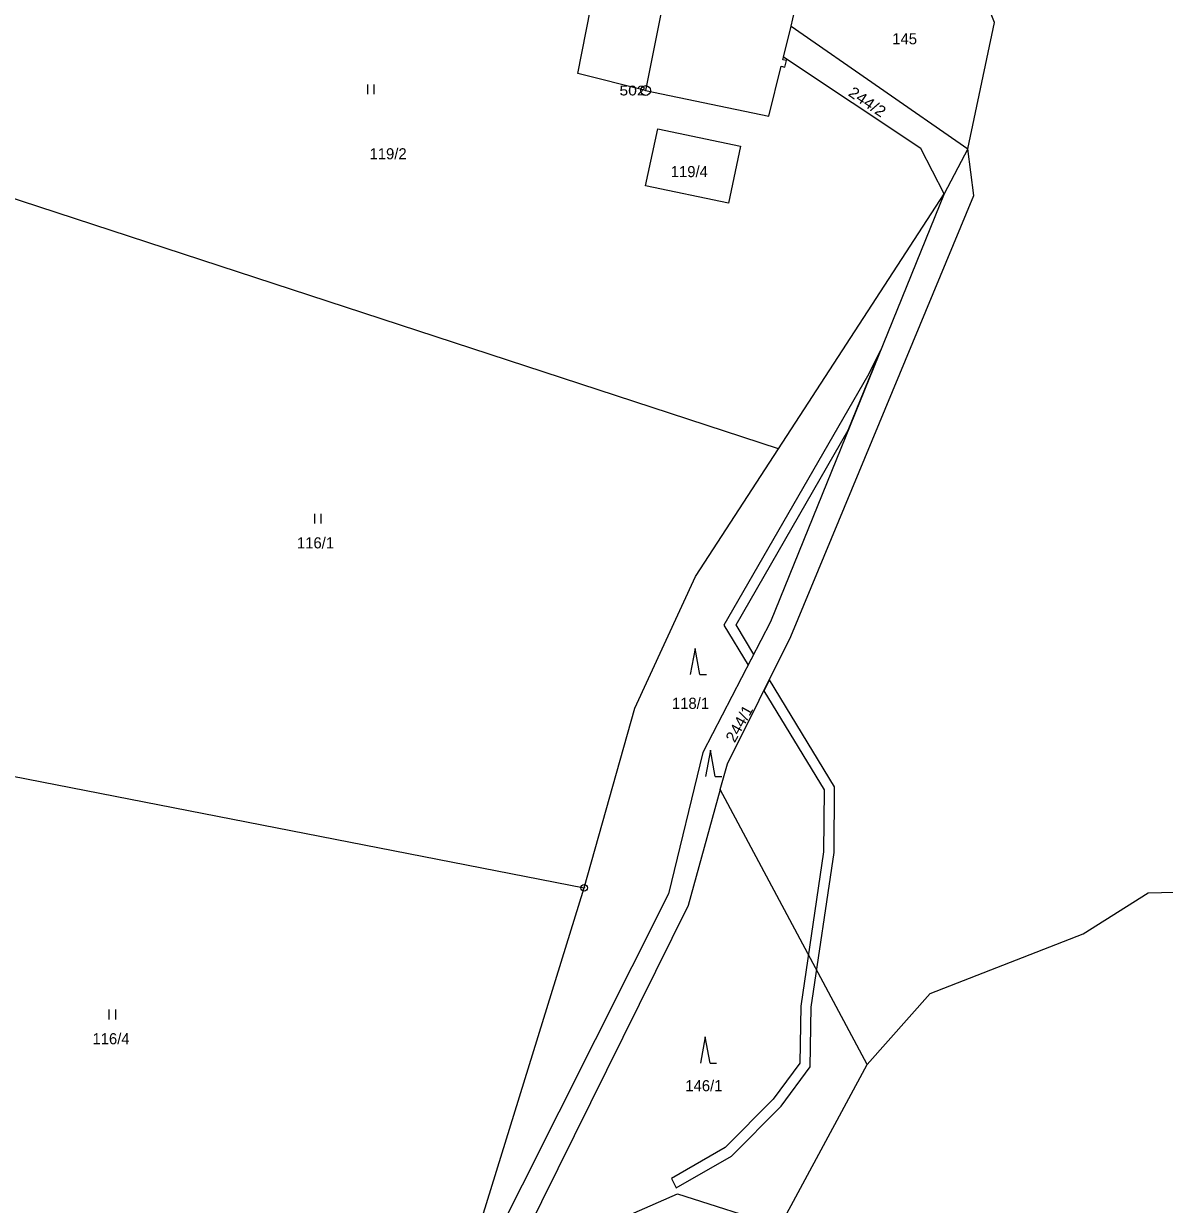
# Model space of a CAD drawing. Extents: x -632162 to -629607, y -1101195 to -1098670.
# Drawn here: x -631847.3 to -631672.5, y -1099345.9 to -1099165 of the extents above; entities that cross this region are included whole.
import ezdxf
from ezdxf.enums import TextEntityAlignment as Align

# ---------------------------------------------------------------- set-up
doc = ezdxf.new("R2010")
doc.units = 0
doc.header["$LTSCALE"] = 0.68
for name, color, linetype, lineweight in [('1', 7, 'Continuous', 25), ('13', 7, 'Continuous', 13), ('3', 7, 'Continuous', 25), ('8', 7, 'Continuous', 25)]:
    doc.layers.add(name, color=color, linetype=linetype, lineweight=lineweight)
doc.layers.add('2', color=7, linetype='Continuous')

msp = doc.modelspace()

# ---------------------------------------------------------------- linework, layer by layer
at = {"layer": '1'}
for p, q in [((-631729.7, -1099165.43), (-631702.64, -1099184.24)), ((-631731.64, -1099230.17), (-631706.26, -1099191.13)), ((-631862.77, -1099277.6), (-631761.39, -1099297.42))]:
    msp.add_line(p, q, dxfattribs=at)
for points in [[(-631751.98, -1099175.29), (-631762.35, -1099172.67), (-631759.79, -1099159.42), (-631759.55, -1099153.52), (-631762.37, -1099148.37), (-631767.41, -1099145.48), (-631784.49, -1099142.91), (-631791.78, -1099142.74), (-631798.56, -1099143.3)], [(-631729.42, -1099164.29), (-631726.24, -1099151.44), (-631745.62, -1099145.76), (-631748.79, -1099157.18), (-631748.51, -1099157.88), (-631751.98, -1099175.29)], [(-631702.64, -1099184.24), (-631698.52, -1099164.87), (-631700.96, -1099158.83)], [(-631730.88, -1099170.16), (-631729.7, -1099165.43), (-631729.42, -1099164.29)], [(-631751.98, -1099175.29), (-631733.12, -1099179.2), (-631731.22, -1099171.55), (-631730.66, -1099171.69), (-631730.39, -1099170.71), (-631730.98, -1099170.57), (-631730.88, -1099170.16)], [(-631706.26, -1099191.13), (-631709.81, -1099184.15), (-631730.88, -1099170.16)], [(-631740.55, -1099282.38), (-631739.45, -1099278.42), (-631729.73, -1099258.93), (-631701.72, -1099191.37), (-631702.64, -1099184.24), (-631706.26, -1099191.13)], [(-631761.39, -1099297.42), (-631753.62, -1099269.88), (-631744.34, -1099249.71), (-631731.64, -1099230.17), (-631853.29, -1099190.4)], [(-631706.26, -1099191.13), (-631732.85, -1099256.7), (-631743.2, -1099276.7), (-631748.5, -1099298.34), (-631776.5, -1099354.15), (-631782.92, -1099366.94)], [(-631718.05, -1099324.49), (-631708.37, -1099313.64), (-631684.97, -1099304.46), (-631674.98, -1099298.2), (-631623.89, -1099296.9), (-631609.58, -1099298.27), (-631580.97, -1099271.56)], [(-631740.55, -1099282.38), (-631745.49, -1099300.12), (-631772.92, -1099355.62)], [(-631772.92, -1099355.62), (-631747.09, -1099344.29), (-631731.43, -1099349.31), (-631718.05, -1099324.49), (-631740.55, -1099282.38)], [(-631810.08, -1099357.71), (-631808.85, -1099353.41), (-631781.37, -1099361.94), (-631778.36, -1099352.21), (-631761.39, -1099297.42)]]:
    msp.add_lwpolyline(points, dxfattribs=at)
msp.add_lwpolyline([(-631750.13, -1099181.14), (-631737.47, -1099183.8), (-631739.31, -1099192.56), (-631751.99, -1099189.91)], close=True, dxfattribs=at)
at = {"layer": '13'}
for points in [[(-631738.13, -1099257.16), (-631720.94, -1099227.34), (-631715.93, -1099214.99), (-631718.01, -1099219.05), (-631739.98, -1099257.18), (-631736.25, -1099263.32), (-631735.4, -1099261.66)], [(-631726.76, -1099324.84), (-631726.61, -1099315.71), (-631723.11, -1099292.02), (-631723.05, -1099281.96), (-631733.03, -1099265.55), (-631733.87, -1099267.23), (-631724.65, -1099282.4), (-631724.71, -1099291.9), (-631728.21, -1099315.57), (-631728.36, -1099324.3), (-631732.45, -1099329.82), (-631739.81, -1099337.23), (-631748.03, -1099341.96), (-631747.31, -1099343.38), (-631738.83, -1099338.51), (-631731.23, -1099330.88)]]:
    msp.add_lwpolyline(points, close=True, dxfattribs=at)
at = {"layer": '3'}
for p, q in [((-631794.551, -1099175.86), (-631794.551, -1099174.36)), ((-631793.55, -1099175.86), (-631793.55, -1099174.36)), ((-631802.671, -1099241.63), (-631802.671, -1099240.13)), ((-631801.67, -1099241.63), (-631801.67, -1099240.13)), ((-631743.66, -1099264.76), (-631742.664, -1099264.76)), ((-631741.32, -1099280.35), (-631740.324, -1099280.35)), ((-631834.161, -1099317.59), (-631834.161, -1099316.09)), ((-631833.16, -1099317.59), (-631833.16, -1099316.09)), ((-631742.1, -1099324.27), (-631741.104, -1099324.27))]:
    msp.add_line(p, q, dxfattribs=at)
for points in [[(-631743.66, -1099264.76), (-631744.41, -1099260.76), (-631745.16, -1099264.76)], [(-631741.32, -1099280.35), (-631742.07, -1099276.35), (-631742.82, -1099280.35)], [(-631742.1, -1099324.27), (-631742.85, -1099320.27), (-631743.6, -1099324.27)]]:
    msp.add_lwpolyline(points, dxfattribs=at)
at = {"layer": '8'}
for centre, radius in [((-631751.98, -1099175.2898), 0.75), ((-631751.98, -1099175.2898), 0.03), ((-631761.39, -1099297.4199), 0.5), ((-631761.39, -1099297.4199), 0.0303)]:
    msp.add_circle(centre, radius, dxfattribs=at)

# ---------------------------------------------------------------- texts
at = {"layer": '2'}
for s, p in [('145', (-631712.299, -1099168.21)), ('119/2', (-631791.44, -1099185.83)), ('119/4', (-631745.29, -1099188.56)), ('116/1', (-631802.56, -1099245.43)), ('118/1', (-631745.11, -1099270.01)), ('116/4', (-631833.89, -1099321.39)), ('146/1', (-631743.06, -1099328.59))]:
    msp.add_text(s, height=1.7, dxfattribs=at).set_placement(p, align=Align.CENTER)
for s, rotation, width, p in [('244/2', 326, 1.1, (-631718.4878, -1099177.7276)), ('244/1', 61, 1.05, (-631736.8941, -1099272.6866))]:
    msp.add_text(s, height=1.7, rotation=rotation, dxfattribs=dict(at, width=width)).set_placement(p, align=Align.CENTER)
at = {"layer": '8', "width": 1.2}
msp.add_text('502', height=1.5, dxfattribs=at).set_placement((-631751.98, -1099176.04), align=Align.RIGHT)

doc.saveas('drawing.dxf')
